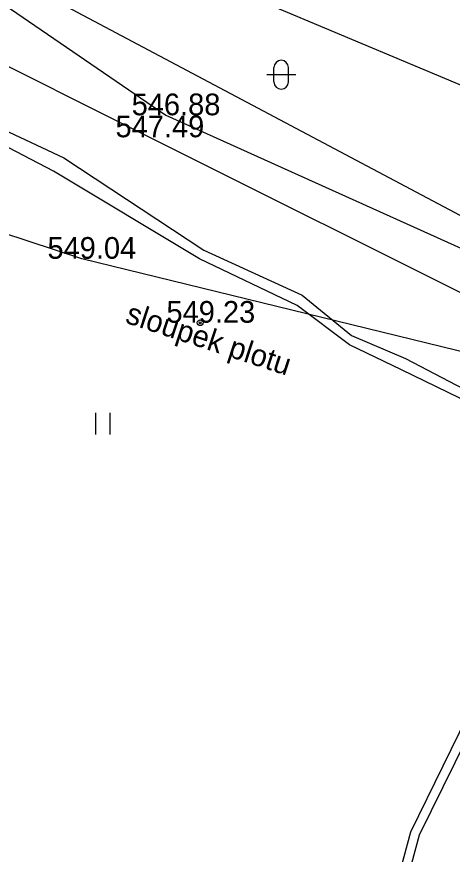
# Model space of a CAD drawing. Extents: x -669995 to -669686, y -1125551 to -1125263.
# Drawn here: x -669860.35 to -669845.3, y -1125387.03 to -1125358.09 of the extents above; entities that cross this region are included whole.
import ezdxf

# ---------------------------------------------------------------- set-up
doc = ezdxf.new("R2010")
doc.units = 0
for name, color, linetype in [('G_Bod_tecka', 7, 'Continuous'), ('G_Bod_vyska', 7, 'Continuous'), ('G_Breh_Teren', 7, 'Continuous'), ('G_Poznamky_odkaz', 7, 'Continuous'), ('G_Site-Sloupy', 7, 'Continuous'), ('G_Z_ELsilove_zrusene', 7, 'Continuous'), ('G_Zelen-Znacky', 7, 'Continuous')]:
    doc.layers.add(name, color=color, linetype=linetype)

msp = doc.modelspace()

# ---------------------------------------------------------------- linework, layer by layer
at = {"layer": 'G_Bod_tecka'}
for p, q in [((-669855.2, -1125361.49), (-669855.2, -1125361.49)), ((-669855.77, -1125362.25), (-669855.77, -1125362.25)), ((-669858.1, -1125366.45), (-669858.1, -1125366.45)), ((-669854.01, -1125368.66), (-669854.01, -1125368.66))]:
    msp.add_line(p, q, dxfattribs=at)
at = {"layer": 'G_Breh_Teren'}
msp.add_line((-669843.53, -1125370.01), (-669858.1, -1125366.45), dxfattribs=at)
for points in [[(-669863.73, -1125348.82), (-669860.89, -1125350.5), (-669852.21, -1125357.41), (-669841.42, -1125361.95), (-669834.66, -1125365.21)], [(-669865.67, -1125352.89), (-669860.32, -1125356.82), (-669843.15, -1125365.95)], [(-669866.2, -1125353.71), (-669861.01, -1125357.51), (-669855.2, -1125361.49), (-669843.47, -1125366.78)], [(-669836.15, -1125369.71), (-669839.86, -1125369.09), (-669843.83, -1125368.22), (-669855.77, -1125362.25), (-669862.27, -1125359), (-669865.77, -1125357.35)], [(-669858.1, -1125366.45), (-669867.24, -1125363.45)]]:
    msp.add_lwpolyline(points, dxfattribs=at)
at = {"layer": 'G_Site-Sloupy'}
for radius in [0.1, 0.0348]:
    msp.add_circle((-669854.01, -1125368.66), radius, dxfattribs=at)
at = {"layer": 'G_Z_ELsilove_zrusene'}
for points in [[(-669863.295, -1125360.816), (-669858.717, -1125362.962), (-669853.883, -1125366.153), (-669850.486, -1125367.71), (-669848.778, -1125369.103), (-669846.912, -1125369.899), (-669844.916, -1125370.944), (-669843.621, -1125372.127), (-669843.116, -1125373.389), (-669842.991, -1125374.364), (-669843.625, -1125378.696), (-669844.397, -1125382.214), (-669846.446, -1125386.365), (-669847.762, -1125391.264)], [(-669863.295, -1125360.816), (-669858.717, -1125362.962), (-669853.883, -1125366.153), (-669850.486, -1125367.71), (-669848.778, -1125369.103), (-669846.912, -1125369.899), (-669844.916, -1125370.944), (-669843.621, -1125372.127), (-669843.116, -1125373.389), (-669842.991, -1125374.364), (-669843.625, -1125378.696), (-669844.397, -1125382.214), (-669846.446, -1125386.365), (-669847.762, -1125391.264)], [(-669848.073, -1125391.245), (-669846.736, -1125386.251), (-669844.771, -1125382.262), (-669843.956, -1125378.516), (-669843.46, -1125374.264), (-669843.446, -1125373.566), (-669844.054, -1125372.192), (-669845.04, -1125371.262), (-669847.052, -1125370.29), (-669848.855, -1125369.426), (-669850.664, -1125368.068), (-669854.033, -1125366.453), (-669859.083, -1125363.428), (-669863.5, -1125361.121)], [(-669848.073, -1125391.245), (-669846.736, -1125386.251), (-669844.771, -1125382.262), (-669843.956, -1125378.516), (-669843.46, -1125374.264), (-669843.446, -1125373.566), (-669844.054, -1125372.192), (-669845.04, -1125371.262), (-669847.052, -1125370.29), (-669848.855, -1125369.426), (-669850.664, -1125368.068), (-669854.033, -1125366.453), (-669859.083, -1125363.428), (-669863.5, -1125361.121)]]:
    msp.add_lwpolyline(points, dxfattribs=at)
at = {"layer": 'G_Zelen-Znacky'}
for p, q in [((-669851.46, -1125360.34), (-669851.46, -1125359.84)), ((-669850.96, -1125360.34), (-669850.96, -1125359.84)), ((-669850.71, -1125360.09), (-669851.71, -1125360.09)), ((-669857.62, -1125372.52), (-669857.62, -1125371.77)), ((-669857.12, -1125372.52), (-669857.12, -1125371.77))]:
    msp.add_line(p, q, dxfattribs=at)
for centre, start, end in [((-669851.21, -1125359.84), 0, 180), ((-669851.21, -1125360.34), 180, 0)]:
    msp.add_arc(centre, 0.25, start, end, dxfattribs=at)

# ---------------------------------------------------------------- texts
at = {"layer": 'G_Bod_vyska'}
for s, p in [('546.88', (-669856.378, -1125361.49)), ('547.49', (-669856.936, -1125362.25)), ('549.04', (-669859.288, -1125366.45)), ('549.23', (-669855.176, -1125368.66))]:
    msp.add_text(s, height=0.75, dxfattribs=at).set_placement(p)
at = {"layer": 'G_Poznamky_odkaz'}
msp.add_text('sloupek plotu', height=0.75, rotation=341.8287, dxfattribs=at).set_placement((-669856.632, -1125368.651))

doc.saveas('drawing.dxf')
